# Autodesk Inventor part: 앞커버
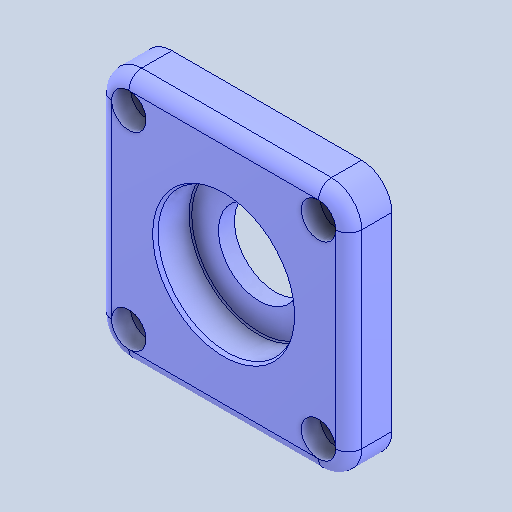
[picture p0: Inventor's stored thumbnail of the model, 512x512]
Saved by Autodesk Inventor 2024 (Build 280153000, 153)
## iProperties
Created: 2026-01
Part Number: 앞커버
Material: 알루미늄 6061
Document SubType Name: Modeling
Designer: 2-10
Density: 2.7 g/cm^3
Appearance: 기본값
Sending System: Autodesk Inventor 2026
Preprocessor: ST-DEVELOPER v20.1
Author: jhkim
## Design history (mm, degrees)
node "앞커버1"
node "솔리드2"
node "솔리드1"
